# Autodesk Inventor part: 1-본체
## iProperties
Created: 2015-01
Part Number: 1-본체
Document SubType Name: Modeling
Designer: Administrator
Density: 2.71 g/cm^3
Material: 알루미늄-6061
Mass: 1021.25 g
Surface Area: 1059.79 cm^2
Volume: 376.845 cm^3
Author: Administrator
